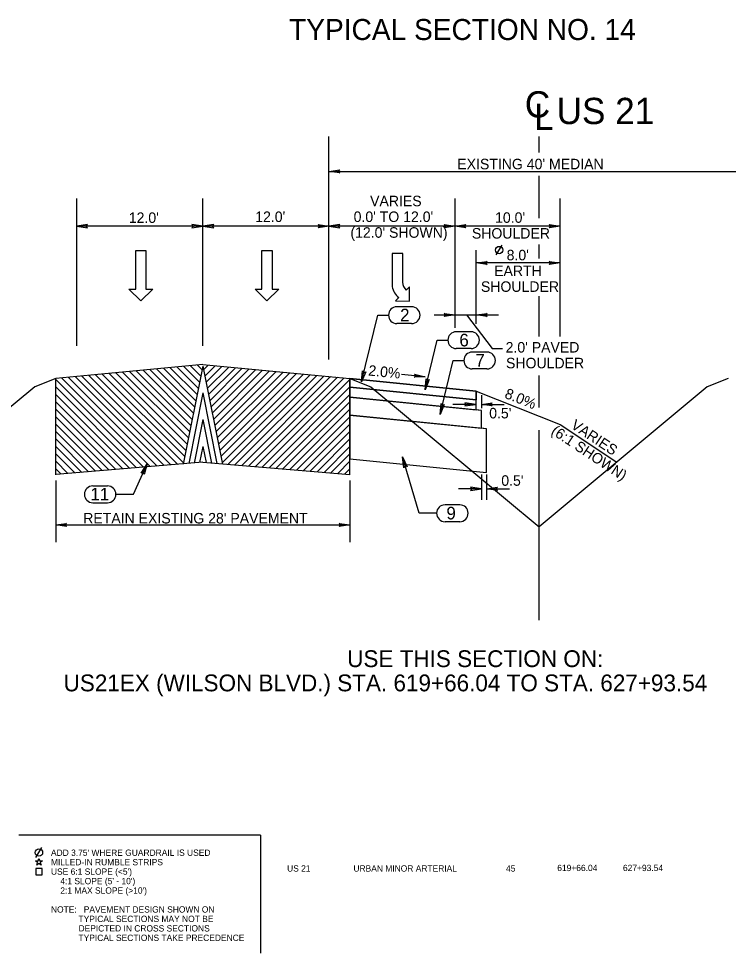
# Model space of a CAD drawing. Extents: x 2003207 to 2014043, y 843846 to 860154.
# Drawn here: x 2013845.7 to 2013913.3, y 844446 to 844534.9 of the extents above; entities that cross this region are included whole.
import ezdxf

# ---------------------------------------------------------------- set-up
doc = ezdxf.new("R2010")
doc.units = 0
for name, color, linetype in [('RD_EX_Road', 7, 'Continuous'), ('RD_EX_Road_txCode', 7, 'Continuous'), ('RD_QTY_Base_Course', 7, 'Continuous'), ('RD_QTY_Intermediate', 7, 'Continuous'), ('RD_QTY_PermVeg', 7, 'Continuous'), ('RD_QTY_Surf_Course', 7, 'Continuous'), ('RD_SHT_Bndy', 7, 'Continuous'), ('RD_SHT_TX', 7, 'Continuous'), ('RD_TX_Misc1', 7, 'Continuous'), ('RD_TX_Misc2', 7, 'Continuous'), ('RD_TX_TypSect', 7, 'Continuous'), ('RD_XS_ExGround', 7, 'Continuous')]:
    doc.layers.add(name, color=color, linetype=linetype)

msp = doc.modelspace()

# ---------------------------------------------------------------- linework, layer by layer
at = {"layer": 'RD_EX_Road'}
for p, q in [((2013863.261, 844502.018), (2013849.261, 844500.705)), ((2013862.741, 844501.969), (2013863.189, 844501.521)), ((2013863.261, 844502.018), (2013877.261, 844500.705)), ((2013863.78, 844501.969), (2013863.333, 844501.521)), ((2013853.044, 844501.06), (2013861.421, 844492.683)), ((2013853.69, 844501.12), (2013861.539, 844493.272)), ((2013854.337, 844501.181), (2013861.657, 844493.861)), ((2013854.983, 844501.242), (2013861.773, 844494.452)), ((2013855.63, 844501.302), (2013861.891, 844495.042)), ((2013856.276, 844501.363), (2013862.009, 844495.631)), ((2013856.923, 844501.423), (2013862.128, 844496.218)), ((2013857.569, 844501.484), (2013862.246, 844496.807)), ((2013858.216, 844501.545), (2013862.364, 844497.397)), ((2013858.862, 844501.605), (2013862.482, 844497.986)), ((2013859.509, 844501.666), (2013862.6, 844498.575)), ((2013860.155, 844501.726), (2013862.718, 844499.164)), ((2013860.802, 844501.787), (2013862.835, 844499.754)), ((2013863.261, 844501.881), (2013861.396, 844492.559)), ((2013861.448, 844501.848), (2013862.953, 844500.343)), ((2013862.095, 844501.908), (2013863.071, 844500.932)), ((2013863.261, 844501.881), (2013865.125, 844492.559)), ((2013864.427, 844501.908), (2013863.451, 844500.932)), ((2013865.073, 844501.848), (2013863.569, 844500.343)), ((2013865.72, 844501.787), (2013863.686, 844499.754)), ((2013866.366, 844501.726), (2013863.804, 844499.164)), ((2013867.013, 844501.666), (2013863.922, 844498.575)), ((2013867.659, 844501.605), (2013864.04, 844497.986)), ((2013868.306, 844501.545), (2013864.158, 844497.397)), ((2013868.952, 844501.484), (2013864.276, 844496.807)), ((2013869.599, 844501.423), (2013864.393, 844496.218)), ((2013870.245, 844501.363), (2013864.511, 844495.629)), ((2013870.892, 844501.302), (2013864.629, 844495.04)), ((2013871.538, 844501.242), (2013864.747, 844494.45)), ((2013872.185, 844501.181), (2013864.865, 844493.861)), ((2013872.831, 844501.12), (2013864.983, 844493.272)), ((2013873.478, 844501.06), (2013865.101, 844492.683)), ((2013849.261, 844491.538), (2013849.261, 844500.705)), ((2013849.261, 844500.6), (2013857.606, 844492.255)), ((2013849.811, 844500.757), (2013858.259, 844492.309)), ((2013850.458, 844500.817), (2013858.912, 844492.364)), ((2013851.104, 844500.878), (2013859.565, 844492.418)), ((2013851.756, 844500.934), (2013860.217, 844492.472)), ((2013852.408, 844500.988), (2013860.87, 844492.527)), ((2013874.113, 844500.988), (2013865.652, 844492.527)), ((2013874.766, 844500.934), (2013866.305, 844492.472)), ((2013875.261, 844500.722), (2013866.957, 844492.418)), ((2013876.064, 844500.817), (2013867.61, 844492.364)), ((2013876.71, 844500.757), (2013868.263, 844492.309)), ((2013877.261, 844500.6), (2013868.915, 844492.255)), ((2013875.403, 844500.864), (2013875.261, 844500.722)), ((2013877.261, 844491.538), (2013877.261, 844500.705)), ((2013849.261, 844499.893), (2013856.954, 844492.2)), ((2013863.261, 844499.332), (2013861.917, 844492.614)), ((2013863.261, 844499.332), (2013864.607, 844492.602)), ((2013877.261, 844499.893), (2013869.568, 844492.2)), ((2013849.261, 844499.186), (2013856.301, 844492.146)), ((2013849.261, 844498.479), (2013855.648, 844492.092)), ((2013877.261, 844499.186), (2013870.221, 844492.146)), ((2013877.261, 844498.479), (2013870.874, 844492.092)), ((2013849.261, 844497.772), (2013854.996, 844492.037)), ((2013877.261, 844497.772), (2013871.526, 844492.037)), ((2013849.261, 844497.065), (2013854.343, 844491.983)), ((2013863.261, 844496.782), (2013862.434, 844492.645)), ((2013863.261, 844496.782), (2013864.088, 844492.645)), ((2013877.261, 844497.065), (2013872.179, 844491.983)), ((2013849.261, 844496.358), (2013853.69, 844491.928)), ((2013877.261, 844496.358), (2013872.832, 844491.928)), ((2013849.261, 844495.65), (2013853.037, 844491.874)), ((2013849.261, 844494.943), (2013852.385, 844491.82)), ((2013877.261, 844495.65), (2013873.484, 844491.874)), ((2013877.261, 844494.943), (2013874.137, 844491.82)), ((2013849.261, 844494.236), (2013851.732, 844491.765)), ((2013863.261, 844494.232), (2013862.952, 844492.689)), ((2013863.261, 844494.232), (2013863.57, 844492.689)), ((2013877.261, 844494.236), (2013874.79, 844491.765)), ((2013849.261, 844493.529), (2013851.079, 844491.711)), ((2013877.261, 844493.529), (2013875.443, 844491.711)), ((2013849.261, 844492.822), (2013850.427, 844491.656)), ((2013863.261, 844492.726), (2013849.261, 844491.559)), ((2013863.261, 844492.726), (2013877.261, 844491.559)), ((2013877.261, 844492.822), (2013876.095, 844491.656)), ((2013849.261, 844492.115), (2013849.774, 844491.602)), ((2013877.261, 844492.115), (2013876.748, 844491.602))]:
    msp.add_line(p, q, dxfattribs=at)
at = {"layer": 'RD_EX_Road_txCode'}
msp.add_line((2013847.384, 844455.107), (2013847.95, 844456.05), dxfattribs=at)
for points in [[(2013847.335, 844454.786), (2013847.589, 844454.786), (2013847.667, 844455.028), (2013847.746, 844454.786), (2013848, 844454.786), (2013847.795, 844454.637), (2013847.873, 844454.395), (2013847.667, 844454.544), (2013847.462, 844454.395), (2013847.54, 844454.637)], [(2013847.367, 844453.452), (2013847.967, 844453.452), (2013847.967, 844454.052), (2013847.367, 844454.052)]]:
    msp.add_lwpolyline(points, close=True, dxfattribs=at)
msp.add_circle((2013847.667, 844455.578), 0.35, dxfattribs=at)
at = {"layer": 'RD_QTY_Base_Course'}
for p, q in [((2013877.261, 844498.925), (2013889.261, 844497.725)), ((2013889.761, 844497.662), (2013889.261, 844497.725)), ((2013889.761, 844495.958), (2013889.761, 844497.662)), ((2013890.261, 844495.895), (2013889.761, 844495.958)), ((2013890.261, 844491.753), (2013890.261, 844495.895)), ((2013877.261, 844493.053), (2013890.261, 844491.753))]:
    msp.add_line(p, q, dxfattribs=at)
for points in [[(2013889.761, 844497.662), (2013877.261, 844498.925), (2013877.261, 844497.22), (2013889.761, 844495.958)], [(2013890.261, 844495.895), (2013877.261, 844497.22), (2013877.261, 844493.053), (2013890.261, 844491.753)]]:
    msp.add_lwpolyline(points, close=True, dxfattribs=at)
at = {"layer": 'RD_QTY_Intermediate'}
for p in [(2013877.261, 844499.872), (2013889.261, 844497.725)]:
    msp.add_line(p, (2013889.261, 844498.672), dxfattribs=at)
msp.add_lwpolyline([(2013889.261, 844498.672), (2013877.261, 844499.872), (2013877.261, 844498.925), (2013889.261, 844497.725)], close=True, dxfattribs=at)
at = {"layer": 'RD_QTY_PermVeg'}
for p, q in [((2013889.261, 844499.505), (2013897.261, 844496.305)), ((2013897.261, 844496.305), (2013902.653, 844492.732))]:
    msp.add_line(p, q, dxfattribs=at)
at = {"layer": 'RD_QTY_Surf_Course'}
for p, q in [((2013877.261, 844500.705), (2013889.261, 844499.505)), ((2013889.261, 844499.505), (2013889.261, 844498.672)), ((2013877.261, 844497.22), (2013889.762, 844495.97))]:
    msp.add_line(p, q, dxfattribs=at)
msp.add_lwpolyline([(2013889.261, 844499.505), (2013877.261, 844500.705), (2013877.261, 844499.872), (2013889.261, 844498.672)], close=True, dxfattribs=at)
at = {"layer": 'RD_SHT_Bndy'}
for q in [(2013845.755, 844457.242), (2013868.755, 844445.992)]:
    msp.add_line((2013868.755, 844457.242), q, dxfattribs=at)
at = {"layer": 'RD_TX_Misc2'}
for p, q in [((2013883.128, 844507.526), (2013881.728, 844507.526)), ((2013883.128, 844505.926), (2013881.728, 844505.926)), ((2013888.778, 844505.14), (2013887.378, 844505.14)), ((2013888.778, 844503.54), (2013887.378, 844503.54)), ((2013890.298, 844503.207), (2013888.898, 844503.207)), ((2013890.298, 844501.607), (2013888.898, 844501.607)), ((2013852.785, 844490.476), (2013854.185, 844490.476)), ((2013852.785, 844488.876), (2013854.185, 844488.876)), ((2013887.704, 844488.672), (2013886.304, 844488.672)), ((2013887.704, 844487.072), (2013886.304, 844487.072))]:
    msp.add_line(p, q, dxfattribs=at)
for centre, start, end in [((2013881.728, 844506.726), 90, 270), ((2013883.128, 844506.726), 270, 90), ((2013887.378, 844504.34), 90, 270), ((2013888.778, 844504.34), 270, 90), ((2013888.898, 844502.407), 90, 270), ((2013890.298, 844502.407), 270, 90), ((2013852.785, 844489.676), 90, 270), ((2013854.185, 844489.676), 270, 90), ((2013886.304, 844487.872), 90, 270), ((2013887.704, 844487.872), 270, 90)]:
    msp.add_arc(centre, 0.8, start, end, dxfattribs=at)
at = {"layer": 'RD_TX_TypSect'}
for p, q in [((2013875.261, 844502.509), (2013875.261, 844523.721)), ((2013895.261, 844522.192), (2013895.261, 844523.721)), ((2013875.261, 844520.411), (2013915.261, 844520.411)), ((2013895.261, 844515.956), (2013895.261, 844520.002)), ((2013851.261, 844503.794), (2013851.261, 844517.819)), ((2013863.261, 844503.794), (2013863.261, 844517.819)), ((2013887.261, 844505.523), (2013887.261, 844517.819)), ((2013897.261, 844504.687), (2013897.261, 844517.819)), ((2013863.261, 844515.195), (2013851.261, 844515.195)), ((2013875.261, 844515.195), (2013863.261, 844515.195)), ((2013887.261, 844515.195), (2013875.261, 844515.195)), ((2013897.261, 844515.195), (2013887.261, 844515.195)), ((2013889.261, 844505.892), (2013889.261, 844512.902)), ((2013891.175, 844512.453), (2013891.741, 844513.396)), ((2013895.261, 844512.109), (2013895.261, 844513.441)), ((2013881.288, 844512.6), (2013881.288, 844509.435)), ((2013882.278, 844512.6), (2013881.288, 844512.6)), ((2013882.278, 844509.855), (2013882.278, 844512.6)), ((2013897.261, 844511.695), (2013889.261, 844511.695)), ((2013882.938, 844509.42), (2013882.623, 844509.105)), ((2013882.923, 844508.07), (2013882.938, 844509.42)), ((2013881.918, 844508.4), (2013881.603, 844508.085)), ((2013895.261, 844504.687), (2013895.261, 844508.521)), ((2013881.603, 844508.085), (2013882.923, 844508.07)), ((2013885.261, 844506.745), (2013891.405, 844506.745)), ((2013884.428, 844500.856), (2013882.151, 844501.083)), ((2013895.261, 844497.938), (2013895.261, 844500.988)), ((2013889.761, 844499.099), (2013889.761, 844497.87)), ((2013889.231, 844498.239), (2013887.063, 844498.239)), ((2013889.761, 844498.239), (2013891.928, 844498.239)), ((2013895.261, 844477.708), (2013895.261, 844495.767)), ((2013889.761, 844491.571), (2013889.761, 844489.148)), ((2013890.261, 844491.571), (2013890.261, 844489.148)), ((2013849.261, 844490.997), (2013849.261, 844485.127)), ((2013877.261, 844490.997), (2013877.261, 844485.127)), ((2013889.761, 844490.199), (2013887.593, 844490.199)), ((2013890.261, 844490.199), (2013892.428, 844490.199)), ((2013849.261, 844486.759), (2013877.261, 844486.759))]:
    msp.add_line(p, q, dxfattribs=at)
for points in [[(2013875.261, 844520.411), (2013876.3, 844520.561), (2013876.14, 844520.411), (2013876.3, 844520.261)], [(2013851.261, 844515.195), (2013852.3, 844515.045), (2013852.14, 844515.195), (2013852.3, 844515.345)], [(2013863.261, 844515.195), (2013862.222, 844515.345), (2013862.382, 844515.195), (2013862.222, 844515.045)], [(2013863.261, 844515.195), (2013864.3, 844515.045), (2013864.14, 844515.195), (2013864.3, 844515.345)], [(2013875.261, 844515.195), (2013874.222, 844515.045), (2013874.382, 844515.195), (2013874.222, 844515.345)], [(2013875.261, 844515.195), (2013876.3, 844515.045), (2013876.14, 844515.195), (2013876.3, 844515.345)], [(2013887.261, 844515.195), (2013886.222, 844515.045), (2013886.382, 844515.195), (2013886.222, 844515.345)], [(2013887.261, 844515.195), (2013888.3, 844515.345), (2013888.14, 844515.195), (2013888.3, 844515.045)], [(2013897.261, 844515.195), (2013896.222, 844515.045), (2013896.382, 844515.195), (2013896.222, 844515.345)], [(2013856.883, 844512.882), (2013857.843, 844512.882), (2013857.843, 844509.213), (2013858.494, 844509.213), (2013857.363, 844508.082), (2013856.231, 844509.213), (2013856.883, 844509.213)], [(2013868.883, 844512.882), (2013869.843, 844512.882), (2013869.843, 844509.213), (2013870.494, 844509.213), (2013869.363, 844508.082), (2013868.231, 844509.213), (2013868.883, 844509.213)], [(2013889.261, 844511.695), (2013890.3, 844511.845), (2013890.14, 844511.695), (2013890.3, 844511.545)], [(2013897.261, 844511.695), (2013896.222, 844511.545), (2013896.382, 844511.695), (2013896.222, 844511.845)], [(2013887.261, 844506.745), (2013886.222, 844506.595), (2013886.382, 844506.745), (2013886.222, 844506.895)], [(2013889.261, 844506.745), (2013890.3, 844506.895), (2013890.14, 844506.745), (2013890.3, 844506.595)], [(2013878.363, 844500.368), (2013878.465, 844501.413), (2013878.572, 844501.222), (2013878.756, 844501.342)], [(2013884.428, 844500.856), (2013883.379, 844500.81), (2013883.554, 844500.943), (2013883.409, 844501.108)], [(2013884.413, 844499.618), (2013884.515, 844500.663), (2013884.622, 844500.472), (2013884.806, 844500.592)], [(2013889.231, 844498.239), (2013888.192, 844498.389), (2013888.352, 844498.239), (2013888.192, 844498.089)], [(2013889.761, 844498.239), (2013890.8, 844498.389), (2013890.64, 844498.239), (2013890.8, 844498.089)], [(2013885.831, 844497.266), (2013885.932, 844498.311), (2013886.04, 844498.12), (2013886.224, 844498.239)], [(2013882.251, 844493.249), (2013882.689, 844492.296), (2013882.5, 844492.407), (2013882.401, 844492.211)], [(2013857.948, 844492.569), (2013857.662, 844491.559), (2013857.59, 844491.766), (2013857.388, 844491.681)], [(2013889.761, 844490.199), (2013888.722, 844490.349), (2013888.882, 844490.199), (2013888.722, 844490.049)], [(2013890.261, 844490.199), (2013891.3, 844490.349), (2013891.14, 844490.199), (2013891.3, 844490.049)], [(2013849.261, 844486.759), (2013850.3, 844486.909), (2013850.14, 844486.759), (2013850.3, 844486.609)], [(2013877.261, 844486.759), (2013876.222, 844486.609), (2013876.382, 844486.759), (2013876.222, 844486.909)]]:
    msp.add_lwpolyline(points, close=True, dxfattribs=at)
for points in [[(2013878.363, 844500.368), (2013879.92, 844506.726), (2013880.928, 844506.726)], [(2013888.339, 844506.745), (2013890.791, 844503.546), (2013891.779, 844503.546)], [(2013884.413, 844499.618), (2013885.569, 844504.34), (2013886.578, 844504.34)], [(2013885.831, 844497.266), (2013887.089, 844502.407), (2013888.098, 844502.407)], [(2013885.504, 844487.872), (2013883.838, 844487.872), (2013882.251, 844493.249)], [(2013854.985, 844489.676), (2013856.65, 844489.676), (2013857.948, 844492.569)]]:
    msp.add_lwpolyline(points, dxfattribs=at)
msp.add_circle((2013891.458, 844512.925), 0.35, dxfattribs=at)
for centre, radius, start, end in [((2013882.84, 844509.672), 1.576, 188.67607, 233.98777), ((2013883.255, 844509.852), 0.983, 180, 229.65818)]:
    msp.add_arc(centre, radius, start, end, dxfattribs=at)
at = {"layer": 'RD_XS_ExGround'}
for p, q in [((2013849.261, 844500.705), (2013847.261, 844499.905)), ((2013877.261, 844500.705), (2013879.261, 844499.905)), ((2013913.261, 844500.705), (2013911.261, 844499.905)), ((2013847.261, 844499.905), (2013831.261, 844486.572)), ((2013879.261, 844499.905), (2013895.261, 844486.572)), ((2013911.261, 844499.905), (2013895.261, 844486.572))]:
    msp.add_line(p, q, dxfattribs=at)

# ---------------------------------------------------------------- texts
at = {"layer": 'RD_EX_Road_txCode'}
for s, height, p in [('USE THIS SECTION ON:', 1.6, (2013876.995, 844473.231)), ('US21EX (WILSON BLVD.) STA. 619+66.04 TO STA. 627+93.54', 1.6, (2013850.01, 844470.926)), ("ADD 3.75' WHERE GUARDRAIL IS USED", 0.6, (2013848.808, 844455.268)), ('MILLED-IN RUMBLE STRIPS', 0.6, (2013848.808, 844454.368)), ("USE 6:1 SLOPE (<5')", 0.6, (2013848.808, 844453.468)), ("    4:1 SLOPE (5' - 10')", 0.6, (2013848.808, 844452.568)), ("    2:1 MAX SLOPE (>10')", 0.6, (2013848.808, 844451.668)), ('NOTE:   PAVEMENT DESIGN SHOWN ON', 0.6, (2013848.808, 844449.868)), (' TYPICAL SECTIONS MAY NOT BE ', 0.6, (2013851.208, 844448.968)), (' DEPICTED IN CROSS SECTIONS', 0.6, (2013851.208, 844448.068)), (' TYPICAL SECTIONS TAKE PRECEDENCE', 0.6, (2013851.208, 844447.168))]:
    msp.add_text(s, height=height, dxfattribs=at).set_placement(p)
at = {"layer": 'RD_SHT_TX'}
for s, p in [('US 21', (2013871.276, 844453.768)), ('URBAN MINOR ARTERIAL', (2013877.588, 844453.768)), ('45', (2013892.109, 844453.768)), ('619+66.04', (2013896.987, 844453.817)), ('627+93.54', (2013903.237, 844453.817))]:
    msp.add_text(s, height=0.6, dxfattribs=at).set_placement(p)
at = {"layer": 'RD_TX_Misc1'}
for s, p in [('C', (2013893.898, 844525.539)), ('L', (2013894.775, 844524.358)), ('US 21', (2013896.924, 844524.911))]:
    msp.add_text(s, height=2.5, dxfattribs=at).set_placement(p)
at = {"layer": 'RD_TX_Misc2'}
for s, p in [('2', (2013882.033, 844506.141)), ('6', (2013887.671, 844503.756)), ('7', (2013889.191, 844501.822)), ('11', (2013852.565, 844489.091)), ('9', (2013886.44, 844487.287))]:
    msp.add_text(s, height=1.2, dxfattribs=at).set_placement(p)
at = {"layer": 'RD_TX_TypSect'}
for s, height, p in [('TYPICAL SECTION NO. 14', 2, (2013871.466, 844532.912)), ("EXISTING 40' MEDIAN", 1, (2013887.472, 844520.609)), ('VARIES', 1, (2013879.175, 844517.094)), ("12.0'", 1, (2013856.215, 844515.503)), ("12.0'", 1, (2013868.246, 844515.594)), ("0.0' TO 12.0'", 1, (2013877.609, 844515.594)), ("10.0'", 1, (2013891.068, 844515.514)), ("(12.0' SHOWN)", 1, (2013877.301, 844514.094)), ('SHOULDER', 1, (2013888.861, 844514.014)), ("8.0'", 1, (2013892.17, 844511.945)), ('EARTH', 1, (2013890.981, 844510.445)), ('SHOULDER', 1, (2013889.722, 844508.945)), ("2.0' PAVED", 1, (2013892.072, 844503.167)), ('SHOULDER', 1, (2013892.111, 844501.667)), ("0.5'", 1, (2013890.508, 844496.901)), ("0.5'", 1, (2013891.659, 844490.488)), ("RETAIN EXISTING 28' PAVEMENT", 1, (2013851.877, 844486.901))]:
    msp.add_text(s, height=height, dxfattribs=at).set_placement(p)
for s, rotation, p in [('2.0%', 354.28941, (2013878.972, 844500.986)), ('8.0%', 338.19859, (2013891.901, 844498.882)), ('VARIES', 326.46577, (2013898.203, 844496.034)), ('(6:1 SHOWN)', 326.46577, (2013896.318, 844495.484))]:
    msp.add_text(s, height=1, rotation=rotation, dxfattribs=at).set_placement(p)

doc.saveas('drawing.dxf')
